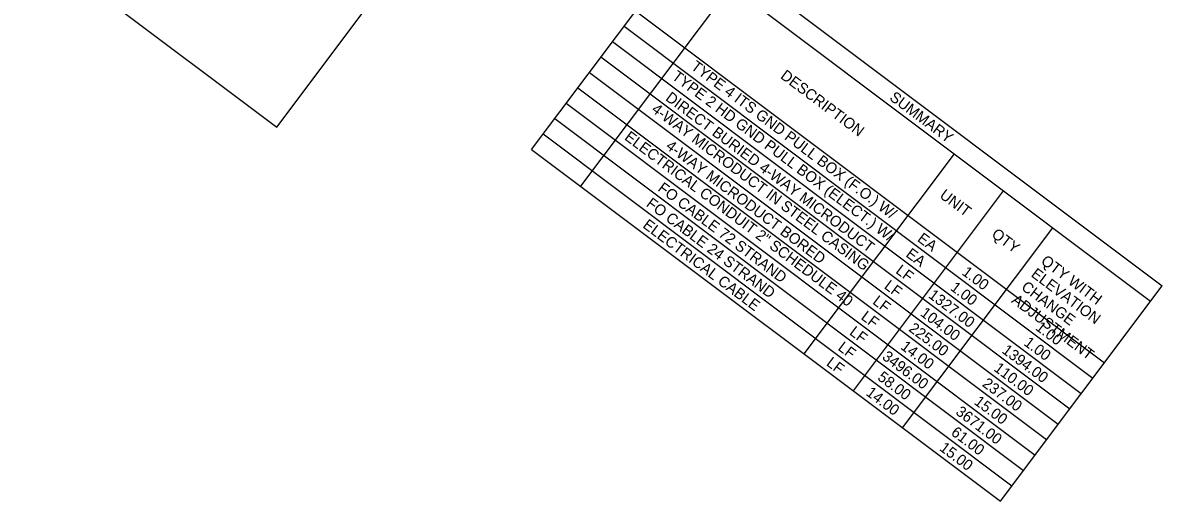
# Model space of a CAD drawing. Extents: x 626494 to 629419, y 365986 to 369334.
# Drawn here: x 627532.6 to 627913.4, y 368872.1 to 369032.1 of the extents above; entities that cross this region are included whole.
import ezdxf

# ---------------------------------------------------------------- set-up
doc = ezdxf.new("R2010")
doc.units = 0
doc.layers.add('Default', color=7, linetype='Continuous')

msp = doc.modelspace()

# ---------------------------------------------------------------- linework, layer by layer
at = {"layer": 'Default'}
for p, q in [((627617.47, 368997.22), (627717.94, 369131.01)), ((627702.65, 368989.78), (627756.74, 369061.82)), ((627756.74, 369061.82), (627913.43, 368944.17)), ((627532.57, 369060.98), (627617.47, 368997.22)), ((627752.88, 369056.68), (627909.57, 368939.02)), ((627719.11, 368977.42), (627769.35, 369044.31)), ((627737.42, 369036.1), (627894.11, 368918.44)), ((627733.56, 369030.95), (627890.25, 368913.29)), ((627729.69, 369025.8), (627886.38, 368908.15)), ((627725.83, 369020.66), (627882.52, 368903)), ((627721.97, 369015.51), (627878.66, 368897.85)), ((627718.1, 369010.37), (627874.79, 368892.71)), ((627714.24, 369005.22), (627870.93, 368887.56)), ((627710.37, 369000.08), (627867.06, 368882.42)), ((627706.51, 368994.93), (627863.2, 368877.27)), ((627702.65, 368989.78), (627859.34, 368872.13)), ((627793.73, 368921.39), (627843.96, 368988.29)), ((627810.19, 368909.03), (627860.43, 368975.92)), ((627826.66, 368896.66), (627876.89, 368963.56)), ((627859.34, 368872.13), (627913.43, 368944.17))]:
    msp.add_line(p, q, dxfattribs=at)

# ---------------------------------------------------------------- texts
for s, p in [('TYPE 2 HD GND PULL BOX (ELECT.) W/', (627749.27, 369013.54)), ('TYPE 4 ITS GND PULL BOX (F.O.) W/', (627755.61, 369016.83)), ('DESCRIPTION', (627785.55, 369013.78)), ('DIRECT BURIED 4-WAY MICRODUCT', (627747.14, 369006.41)), ('SUMMARY', (627821.99, 369006.54)), ('4-WAY MICRODUCT IN STEEL CASING', (627742.46, 369002.56)), ('ELECTRICAL CONDUIT 2" SCHEDULE 40', (627733.42, 368993.26)), ('4-WAY MICRODUCT BORED', (627747.22, 368990.26)), ('FO CABLE 72 STRAND ', (627744.57, 368976.16)), ('UNIT', (627838.76, 368973.83)), ('FO CABLE 24 STRAND ', (627740.7, 368971.01)), ('ELECTRICAL CABLE ', (627739.52, 368963.85)), ('QTY', (627856.11, 368960.8)), ('EA', (627831.31, 368959.3)), ('EA', (627827.45, 368954.15)), ('LF', (627824.07, 368948.64)), ('QTY WITH', (627872.6, 368951.82)), ('1.00', (627846.21, 368948.12)), ('ELEVATION', (627869.33, 368947.47)), ('LF', (627820.21, 368943.5)), ('1.00', (627842.34, 368942.97)), ('CHANGE', (627866.06, 368943.12)), ('LF', (627816.35, 368938.35)), ('1327.00', (627835, 368940.43)), ('ADJUSTMENT', (627862.79, 368938.76)), ('104.00', (627832.3, 368934.42)), ('LF', (627812.48, 368933.2)), ('LF', (627808.62, 368928.06)), ('225.00', (627828.43, 368929.27)), ('1.00', (627870.78, 368929.67)), ('LF', (627804.75, 368922.91)), ('14.00', (627825.73, 368923.26)), ('1.00', (627866.91, 368924.52)), ('3496.00', (627819.55, 368919.85)), ('1394.00', (627859.57, 368921.98)), ('LF', (627800.89, 368917.77)), ('110.00', (627856.87, 368915.97)), ('58.00', (627818, 368912.97)), ('237.00', (627853, 368910.82)), ('14.00', (627814.14, 368907.82)), ('15.00', (627850.3, 368904.81)), ('3671.00', (627844.12, 368901.4)), ('61.00', (627842.57, 368894.52)), ('15.00', (627838.71, 368889.37))]:
    msp.add_text(s, height=3.63, rotation=323.0968, dxfattribs=at).set_placement(p)

doc.saveas('drawing.dxf')
